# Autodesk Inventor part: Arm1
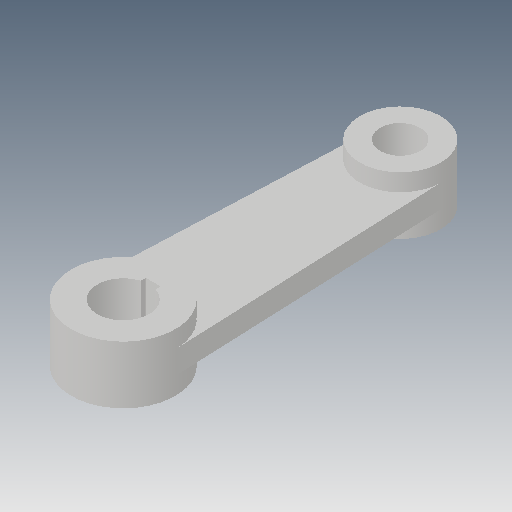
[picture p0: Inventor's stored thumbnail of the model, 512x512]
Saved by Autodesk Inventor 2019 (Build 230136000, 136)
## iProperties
Created: 2016-05
Part Number: Arm1
Material: Generic
Document SubType Name: Modeling
Designer: CADCIM
Density: 1 g/cm^3
Appearance: Default
Author: CADCIM
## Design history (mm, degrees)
sketch "Sketch1"
  geometry: C1 r 56.25 at (0, 0); C2 r 28 at (0, 0); C3 r 43.75 at (0, -300); C4 r 21.75 at (0, -300); 1 further point
  constraints: 4 centre point, 3 coincident
  dimensions: "d0" = 112.5 diameter of C1; "d1" = 56 diameter of C2; "d2" = 87.5 diameter of C3; "d3" = 43.5 diameter of C4; "d4" = 300 distance of C4.centre C2.centre
extrude "Extrusion1" new body sketch "Sketch1" stored distance "d5" = 62.5; taper "d6" = 0 deg
sketch "Sketch2"
  geometry: L1 (56.201, -2.344)-(43.712, -301.823); L2 (-56.201, -2.344)-(-43.712, -301.823); A1 r 56.25 centre (0, 0) between (-56.201, -2.344) and (56.201, -2.344); A2 r 43.75 centre (0, -300) between (43.712, -301.823) and (-43.712, -301.823); 3 further points
  constraints: 4 end point, 4 point on circle, 2 centre point, 2 coincident
extrude "Extrusion2" join sketch "Sketch2" stored distance "d7" = 25; taper "d8" = 0 deg
sketch "Sketch3"
  geometry: L1 (0, 0)-(0, 99.622); L2 (-8, 26.833)-(8, 26.833); L3 (8, 26.833)-(8, 32.3); L4 (8, 32.3)-(-8, 32.3); L5 (-8, 32.3)-(-8, 26.833); L6 (0, 0)-(0, -28); A1 r 28 centre (0, 0) between (-8, 26.833) and (8, 26.833) reference
  constraints: 12 end point, 3 point on circle, 2 parallel, 2 vertical, 1 horizontal, 1 perpendicular, 1 other
  dimensions: "d10" = 16 distance of L3.end L4.end; "d11" = 60.3 distance from line of L4 L6.end
extrude "Extrusion3" cut sketch "Sketch3" extent not by distance; stored distance "d12" = 25; taper "d13" = 0 deg
fillet "Fillet1" dims "d14" = 0.4
body "Solid1"
